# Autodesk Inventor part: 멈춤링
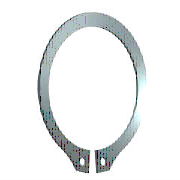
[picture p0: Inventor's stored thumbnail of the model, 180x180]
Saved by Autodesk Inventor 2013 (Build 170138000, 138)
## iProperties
IsCustomPart: 0
Created: 2009-02
Part Number: 멈춤링
Material: 강, 연강
Description: 리테이닝 링(C형)
Document SubType Name: Modeling
Standard: KS B 1336
Designer: KYOUNG IL JANG
Standards Organization: KS
Language: ko-KR
Size Designation: 22 x 1.2
Categories: <MemberInstance><Categories><Category DisplayName="샤프트 부품" InternalName="7f7aeb1f-a693-4053-b835-cee3144e0d98" Mnemonic="SHFT"><Category DisplayName="써클립" Inter
Density: 1 g/cm^3
Author: KYOUNG IL JANG
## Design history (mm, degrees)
sketch "스케치1"
  geometry: L1 (-6, 0)-(6, 0) reference; L2 (0, 20.189)-(0, -80.536) reference; L3 (-48.09, 0)-(48.09, 0) reference; L4 (-0.5, -21.488)-(-0.5, -25.588); L5 (-0.5, -6.54)-(-0.5, -13.29); L6 (-2.795, 2.7)-(3.672, 2.7); L7 (0.5, -6.54)-(0.5, -13.29); L8 (0.5, -21.488)-(0.5, -25.588); C1 r 1 at (-2, -23.437); C2 r 1 at (2, -23.437); A1 r 10.5 centre (0, -11) between (0.5, -21.488) and (-0.5, -21.488); A2 r 13.025 centre (0, -10.325) between (5.149, -22.289) and (-5.149, -22.289); A3 r 14.597 centre (0, -11) between (-2.318, -25.411) and (-0.5, -25.588); A4 r 2 centre (-2, -23.437) between (-3.97, -23.781) and (-2.318, -25.411); A5 r 2 centre (-5.94, -24.126) between (-3.97, -23.781) and (-5.149, -22.289); A6 r 2 centre (5.94, -24.126) between (5.149, -22.289) and (3.97, -23.781); A7 r 2 centre (2, -23.437) between (2.318, -25.411) and (3.97, -23.781); A8 r 14.597 centre (0, -11) between (0.5, -25.588) and (2.318, -25.411)
  constraints: 16 point on circle, 12 end point, 10 centre point, 9 symmetric about line, 5 point on line, 4 tangent, 3 coincident, 2 horizontal, 1 perpendicular, 1 vertical, 5 other
  dimensions: "d0" = 21 diameter of A1 (= ND); "d1" = 4.1 distance of L4.end L4.start (= SRB2); "d6" = 0.5 distance between parallel lines of L2 L5 (= 0.25 x SD5); "d7" = 2.7 distance between parallel lines of L6 L3 (= SRB1); "d8" = 0.675 distance of A1.centre A2.centre (= 0.25 x SRB1); "d9" = 2 radius of A4 (= SD5); "d10" = 2 radius of A5 (= SD5); "d11" = 1.5 distance from line of L4 A4.centre (= 0.75 x SD5); "d12" = 2 diameter of C1 (= SD5); "d13" = 2 diameter of C2 (= SD5); "d14" = 11 distance from line of A1.centre L1 (= 0.5 x WD)
extrude "본체" new body sketch "스케치1" distance "d2" = 1.2 (= SD); taper "d3" = 0 deg
workaxis "Work Axis1"
workplane "Work Plane1"
body "Solid1"
other parameters: "WD" = 22 (= WDMIN) [user parameter; used in 1 equation term], "SD" = 1.2 [user parameter; used in 1 equation term], "SRB1" = 2.7 [user parameter; used in 2 equation terms], "ND" = 21 [user parameter; used in 1 equation term], "SRB2" = 4.1 [user parameter; used in 1 equation term], "SD5" = 2 [user parameter; used in 6 equation terms], "d15" = 0, "d16" = 0, "d17" = 0, "d41" = 0, "d42" = 0, "WDMIN" = 22 [user parameter; used in 1 equation term], "SD3" = 20.5 [user parameter], "WDMAX" = 24 [user parameter]
